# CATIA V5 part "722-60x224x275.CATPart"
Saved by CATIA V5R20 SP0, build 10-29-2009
Part number: 722-60x224x275
Definition: NONE
Nomenclature: 722-60x224x275
Source: Unknown
Description: 722-60x224x275
Bounding box of the stored display mesh (mm): x -30 to 30, y -30 to 30, z -206 to 69
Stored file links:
  C:\Users\Utente\Desktop\IO LAVORO\3D X SITO CF\X SITO\722\722-60x224x275.CATPart
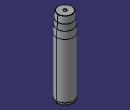
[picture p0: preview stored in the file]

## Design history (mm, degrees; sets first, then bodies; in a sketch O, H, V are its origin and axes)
Body1 "722-60x224x275" (main body)
  Solid1: solid without history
